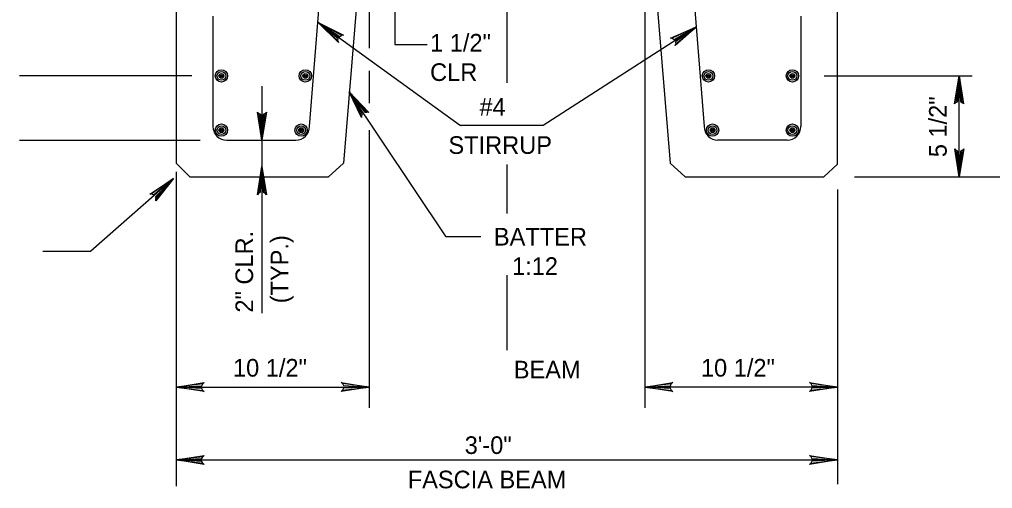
# Model space of a CAD drawing. Extents: x 642009 to 642864, y 298232 to 300014.
# Drawn here: x 642543.6 to 642709.1, y 298526.5 to 298606.3 of the extents above; entities that cross this region are included whole.
import ezdxf

# ---------------------------------------------------------------- set-up
doc = ezdxf.new("R2010")
doc.units = 0
for name, color, linetype in [('1', 7, 'Continuous'), ('10', 7, 'Continuous'), ('15', 7, 'Continuous'), ('2', 7, 'Continuous'), ('22', 7, 'Continuous'), ('3', 7, 'Continuous'), ('43', 7, 'Continuous')]:
    doc.layers.add(name, color=color, linetype=linetype)

msp = doc.modelspace()

# ---------------------------------------------------------------- linework, layer by layer
at = {"layer": '1'}
for p, q in [((642603.1, 298634.24), (642598.74, 298581.89)), ((642570.29, 298632.67), (642570.29, 298581.9)), ((642682.78, 298581.71), (642682.78, 298632.67)), ((642650.81, 298624.19), (642654.33, 298581.89)), ((642570.29, 298581.9), (642572.64, 298579.55)), ((642596.2, 298579.55), (642598.74, 298581.89)), ((642654.33, 298581.89), (642656.87, 298579.55)), ((642680.43, 298579.55), (642682.78, 298581.71)), ((642572.64, 298579.55), (642596.2, 298579.55)), ((642656.87, 298579.55), (642680.43, 298579.55))]:
    msp.add_line(p, q, dxfattribs=at)
for points in [[(642597.8, 298602.7), (642597.86, 298603.07), (642594.46, 298605.82), (642597.8, 298602.7), (642597.88, 298602.4), (642594.46, 298605.82), (642598.13, 298603.44), (642598.45, 298603.61), (642594.46, 298605.82), (642598.77, 298603.64), (642598.45, 298603.61)], [(642654.66, 298603.13), (642654.98, 298602.95), (642658.78, 298605.11), (642654.66, 298603.13), (642654.35, 298603.17), (642658.78, 298605.11), (642655.23, 298602.56), (642655.27, 298602.2), (642658.78, 298605.11), (642655.18, 298601.89), (642655.27, 298602.2)], [(642601.83, 298589.95), (642602, 298590.28), (642599.72, 298594.02), (642601.83, 298589.95), (642601.79, 298589.65), (642599.72, 298594.02), (642602.38, 298590.54), (642602.73, 298590.59), (642599.72, 298594.02), (642603.05, 298590.51), (642602.73, 298590.59)], [(642585.45, 298590.34), (642585.12, 298590.18), (642584.88, 298585.8), (642585.45, 298590.34), (642585.65, 298590.58), (642584.88, 298585.8), (642584.67, 298590.17), (642584.34, 298590.33), (642584.88, 298585.8), (642584.12, 298590.58), (642584.34, 298590.33)], [(642584.31, 298576.76), (642584.64, 298576.93), (642584.88, 298581.3), (642584.31, 298576.76), (642584.11, 298576.53), (642584.88, 298581.3), (642585.1, 298576.94), (642585.42, 298576.78), (642584.88, 298581.3), (642585.64, 298576.53), (642585.42, 298576.78)]]:
    msp.add_lwpolyline(points, dxfattribs=at)
at = {"layer": '10'}
for p, q in [((642626.54, 298641.54), (642626.54, 298595.57)), ((642626.54, 298581.69), (642626.54, 298573.33)), ((642626.54, 298562.84), (642626.54, 298550.1))]:
    msp.add_line(p, q, dxfattribs=at)
at = {"layer": '15'}
for p, q in [((642592.98, 298588.14), (642597.85, 298649.06)), ((642655.2, 298649.39), (642660.09, 298588.14)), ((642576.55, 298606.9), (642576.55, 298588.15)), ((642676.53, 298606.9), (642676.53, 298588.15)), ((642578.89, 298585.8), (642590.64, 298585.8)), ((642674.18, 298585.8), (642662.43, 298585.8))]:
    msp.add_line(p, q, dxfattribs=at)
for centre, start, end in [((642578.89, 298588.15), 180, 270), ((642590.64, 298588.14), 270, 0), ((642662.43, 298588.14), 180, 270), ((642674.18, 298588.15), 270, 0)]:
    msp.add_arc(centre, 2.34, start, end, dxfattribs=at)
at = {"layer": '2'}
for p, q in [((642584.88, 298595), (642584.88, 298585.8)), ((642584.88, 298585.8), (642584.88, 298581.3)), ((642584.88, 298581.3), (642584.88, 298556.36))]:
    msp.add_line(p, q, dxfattribs=at)
at = {"layer": '22'}
for p, q in [((642607.5, 298644.17), (642607.5, 298602.08)), ((642603.1, 298625.74), (642603.1, 298601.46)), ((642649.97, 298625.74), (642649.97, 298540.27)), ((642607.5, 298602.08), (642612.97, 298602.08)), ((642603.1, 298597.6), (642603.1, 298592.11)), ((642572.97, 298596.74), (642543.65, 298596.74)), ((642680.5, 298596.74), (642705.64, 298596.74)), ((642703.45, 298579.55), (642703.45, 298596.74)), ((642616.19, 298569.35), (642599.72, 298594.02)), ((642603.1, 298587.51), (642603.1, 298540.27)), ((642543.65, 298585.8), (642574.36, 298585.8)), ((642569.84, 298579.29), (642555.78, 298566.93)), ((642685.67, 298579.55), (642731.76, 298579.55)), ((642570.29, 298578.41), (642570.29, 298526.93)), ((642682.78, 298577.4), (642682.78, 298527.28)), ((642547.65, 298566.93), (642555.78, 298566.93)), ((642570.29, 298543.81), (642603.1, 298543.81)), ((642682.78, 298543.81), (642649.97, 298543.81)), ((642570.29, 298531.4), (642682.78, 298531.4))]:
    msp.add_line(p, q, dxfattribs=at)
for points in [[(642702.88, 298592.2), (642703.21, 298592.37), (642703.45, 298596.74), (642702.88, 298592.2), (642702.68, 298591.96), (642703.45, 298596.74), (642703.67, 298592.37), (642703.99, 298592.21), (642703.45, 298596.74), (642704.21, 298591.96), (642703.99, 298592.21)], [(642704.02, 298584.09), (642703.69, 298583.92), (642703.45, 298579.55), (642704.02, 298584.09), (642704.22, 298584.33), (642703.45, 298579.55), (642703.23, 298583.92), (642702.91, 298584.08), (642703.45, 298579.55), (642702.69, 298584.33), (642702.91, 298584.08)], [(642566.1, 298576.65), (642566.45, 298576.52), (642569.84, 298579.29), (642566.1, 298576.65), (642565.8, 298576.64), (642569.84, 298579.29), (642566.76, 298576.19), (642566.86, 298575.84), (642569.84, 298579.29), (642566.83, 298575.51), (642566.86, 298575.84)], [(642574.84, 298543.24), (642574.67, 298543.57), (642570.29, 298543.81), (642574.84, 298543.24), (642575.07, 298543.04), (642570.29, 298543.81), (642574.66, 298544.03), (642574.82, 298544.35), (642570.29, 298543.81), (642575.07, 298544.57), (642574.82, 298544.35)], [(642598.56, 298544.38), (642598.73, 298544.05), (642603.1, 298543.81), (642598.56, 298544.38), (642598.33, 298544.58), (642603.1, 298543.81), (642598.74, 298543.6), (642598.58, 298543.27), (642603.1, 298543.81), (642598.33, 298543.06), (642598.58, 298543.27)], [(642654.51, 298543.24), (642654.34, 298543.57), (642649.97, 298543.81), (642654.51, 298543.24), (642654.74, 298543.04), (642649.97, 298543.81), (642654.34, 298544.03), (642654.5, 298544.35), (642649.97, 298543.81), (642654.74, 298544.57), (642654.5, 298544.35)], [(642678.24, 298544.38), (642678.41, 298544.05), (642682.78, 298543.81), (642678.24, 298544.38), (642678, 298544.58), (642682.78, 298543.81), (642678.41, 298543.6), (642678.25, 298543.27), (642682.78, 298543.81), (642678, 298543.06), (642678.25, 298543.27)], [(642574.84, 298530.83), (642574.67, 298531.16), (642570.29, 298531.4), (642574.84, 298530.83), (642575.07, 298530.63), (642570.29, 298531.4), (642574.66, 298531.62), (642574.82, 298531.94), (642570.29, 298531.4), (642575.07, 298532.16), (642574.82, 298531.94)], [(642678.24, 298531.97), (642678.41, 298531.64), (642682.78, 298531.4), (642678.24, 298531.97), (642678, 298532.17), (642682.78, 298531.4), (642678.41, 298531.19), (642678.25, 298530.86), (642682.78, 298531.4), (642678, 298530.65), (642678.25, 298530.86)]]:
    msp.add_lwpolyline(points, dxfattribs=at)
at = {"layer": '3'}
for p, q in [((642594.46, 298605.82), (642618.65, 298588.31)), ((642658.78, 298605.11), (642632.69, 298588.31)), ((642570.29, 298580.4), (642570.29, 298570.13)), ((642570.29, 298571.63), (642570.29, 298571.63))]:
    msp.add_line(p, q, dxfattribs=at)
for centre, radius in [((642577.99, 298596.74), 1.05), ((642577.99, 298596.74), 0.75), ((642577.99, 298596.74), 0.41), ((642592.26, 298596.74), 1.05), ((642592.26, 298596.74), 0.75), ((642592.26, 298596.74), 0.41), ((642660.81, 298596.74), 1.05), ((642660.81, 298596.74), 0.75), ((642660.81, 298596.74), 0.41), ((642675.09, 298596.74), 1.05), ((642675.09, 298596.74), 0.75), ((642675.09, 298596.74), 0.41), ((642577.99, 298596.74), 0.207), ((642577.99, 298596.74), 0.0887), ((642592.26, 298596.74), 0.207), ((642592.26, 298596.74), 0.0887), ((642660.81, 298596.74), 0.207), ((642660.81, 298596.74), 0.0887), ((642675.09, 298596.74), 0.207), ((642675.09, 298596.74), 0.0887), ((642577.99, 298587.51), 1.05), ((642577.99, 298587.51), 0.75), ((642577.99, 298587.51), 0.41), ((642577.99, 298587.51), 0.207), ((642577.99, 298587.51), 0.0887), ((642591.55, 298587.51), 1.05), ((642591.55, 298587.51), 0.75), ((642591.55, 298587.51), 0.41), ((642591.55, 298587.51), 0.207), ((642591.55, 298587.51), 0.0887), ((642661.52, 298587.51), 1.05), ((642661.52, 298587.51), 0.75), ((642661.52, 298587.51), 0.41), ((642661.52, 298587.51), 0.207), ((642661.52, 298587.51), 0.0887), ((642675.09, 298587.51), 1.05), ((642675.09, 298587.51), 0.75), ((642675.09, 298587.51), 0.41), ((642675.09, 298587.51), 0.207), ((642675.09, 298587.51), 0.0887)]:
    msp.add_circle(centre, radius, dxfattribs=at)
at = {"layer": '43'}
for p, q in [((642632.69, 298588.31), (642618.65, 298588.31)), ((642622.12, 298569.35), (642616.19, 298569.35))]:
    msp.add_line(p, q, dxfattribs=at)

# ---------------------------------------------------------------- texts
at = {"layer": '2'}
for s, p in [('2" CLR.', (642583.38, 298556.47)), ('(TYP.)', (642589.38, 298558.05))]:
    msp.add_text(s, height=3, rotation=90, dxfattribs=at).set_placement(p)
at = {"layer": '22'}
for s, p in [('1 1/2"', (642613.48, 298600.88)), ('CLR', (642613.48, 298595.88)), ('10 1/2"', (642579.96, 298545.58)), ('  BEAM', (642625.48, 298545.27))]:
    msp.add_text(s, height=3, dxfattribs=at).set_placement(p)
for s, height, rotation, p in [('#4', 3, 360, (642621.88, 298589.97)), ('5 1/2"', 3, 90, (642701.33, 298582.91)), ('STIRRUP', 3, 360, (642616.6, 298583.47)), ('BATTER', 3, 360, (642624.33, 298567.88)), ('1:12', 3, 360, (642627.42, 298562.88)), ('10 1/2"', 3, 360, (642659.54, 298545.58)), ('3\'-0"', 3, 360, (642619.37, 298532.42)), ('FASCIA BEAM', 2.9997, 360, (642609.68, 298526.58))]:
    msp.add_text(s, height=height, rotation=rotation, dxfattribs=at).set_placement(p)

doc.saveas('drawing.dxf')
